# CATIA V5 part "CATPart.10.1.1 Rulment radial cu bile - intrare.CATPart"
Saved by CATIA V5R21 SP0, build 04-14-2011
Part number: Rulment radial cu bile.1
Bounding box of the stored display mesh (mm): x -30.959 to 30.959, y -8 to 8, z -30.959 to 30.959
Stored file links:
  C:\Users\MIRCEA\Desktop\MOM\Mogan\model\CATPart.10.1.1 Rulment radial cu bile - intrare.CATPart
  D:\My documents\Downloads\DesignTable1.txt
  D:\Nextcloud\Documents\Facultate\Studenti\MOM Robotica\Rulment radial cu bile.txt
  D:\Nextcloud\Documents\Facultate\Studenti\MOM Robotica\Rulment radial cu bile_catalog.txt
  C:\Users\Mogan\Desktop\SIOM ver.2.0, 2013 (2019)\LAB_OM\2019\Lucrari de laborator finale\Lucrari reprezentare suporti rulmenti\Rulment_radial_cu_bile_catalog.txt
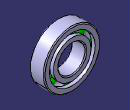
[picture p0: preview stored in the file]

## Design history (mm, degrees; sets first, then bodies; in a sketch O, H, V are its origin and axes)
Parameters
  d = 30 mm
  B = 16 mm
  D = 62 mm
  `grosime inele` = 16 mm {= (D -d )/2}
  Simbol_2 = "6002"
Body1 "inel exterior" (main body)
  Sketch1 on xy-plane, origin (0, 0, 0), H (1, 0, 0), V (0, 1, 0)
    point P1 (25.2857, 3.959)
    line L1 (25.2857, 3.959) -> (25.2857, 8)
    line L2 (25.2857, 8) -> (30, 8)
    line L3 (31, 7) -> (31, -7)
    line L4 (30, -8) -> (25.2857, -8)
    line L5 (25.2857, -8) -> (25.2857, -3.959)
    point P4 (25.2857, -3.959)
    point P5 (23, 0)
    arc A1 centre (23, 0) radius 4.5714 from (25.2857, -3.959) to (25.2857, 3.959) ccw
    arc A2 centre (30, 7) radius 1 from (30, 8) to (31, 7) cw
    arc A3 centre (30, -7) radius 1 from (31, -7) to (30, -8) cw
    radius A1 = 4.5714 {= 2*`grosime inele`  /7}
    distance L1 L3 = 5.7143 {= `grosime inele`  /2-Sketch1.radius(A1) *0.5}
    radius A2 = 1
    radius A3 = 1
    distance L2 L4 = 16 {= B}
    distance L3 V = 31 {= D /2}
    distance P5 V = 23 {= (D +d )/4}
    vertical: L1 V, L3 V, L5 V
    horizontal: L2 H, L4 H
    coincidence: P5 H
    symmetry: L2 L4 H, P4 P1 H
    tangency: A2 L2, A2 L3, A3 L3, A3 L4
  Shaft1: profile Sketch1, axis Sketch1.V, angle 360
Body2 "inel interior"
  Sketch2 on xy-plane, origin (0, 0, 0), H (1, 0, 0), V (0, 1, 0)
    point P1 (20.7143, 3.959)
    line L1 (20.7143, 3.959) -> (20.7143, 8)
    line L2 (20.7143, 8) -> (16, 8)
    line L3 (15, 7) -> (15, -7)
    line L4 (16, -8) -> (20.7143, -8)
    line L5 (20.7143, -8) -> (20.7143, -3.959)
    point P4 (20.7143, -3.959)
    arc A1 centre (23, 0) radius 4.5714 from (20.7143, 3.959) to (20.7143, -3.959) ccw
    point P5 (23, 0)
    arc A2 centre (16, 7) radius 1 from (15, 7) to (16, 8) cw
    arc A3 centre (16, -7) radius 1 from (15, -7) to (16, -8) ccw
    distance L3 V = 15 {= d /2}
    radius A1 = 4.5714 {= 2*`grosime inele`  /7}
    distance L2 L4 = 16 {= B}
    distance L1 L3 = 5.7143 {= `grosime inele`  /2-Sketch2.radius(A1) *0.5}
    radius A2 = 1
    radius A3 = 1
    distance P5 V = 23 {= (D +d )/4}
    vertical: L1 V, L3 V, L5 V
    horizontal: L2 H, L4 H
    coincidence: P5 H
    symmetry: L2 L4 H, P1 P4 H
    tangency: A2 L3, A2 L2, A3 L3, A3 L4
  Shaft2: profile Sketch2, axis Sketch2.V, angle 360
Body3 "bile"
  Sketch3 on zx-plane, origin (0, 0, 0), H (-1, 0, 0), V (0, 0, 1)
    arc A1 centre (0, 23) radius 4.5714 from (0, 18.4286) to (0, 27.5714) ccw
    point P1 (0, 23)
    line L1 (0, 27.5714) -> (0, 18.4286)
    distance H P1 = 23 {= (d +D )/4}
    radius A1 = 4.5714 {= Sketch1.radius(A1)}
    coincidence: P1 V, L1 V
    vertical: L1 V
  Shaft3: profile Sketch3, axis Sketch3.L1, angle 360
  CircPattern1: of Shaft3, instances 8, angular step 45 {= 360.0*1 deg/CircPattern1.AngularNumber}, axis from Y axis
Relations
  design table, configuration 1, drives d, D, B (deactivated)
